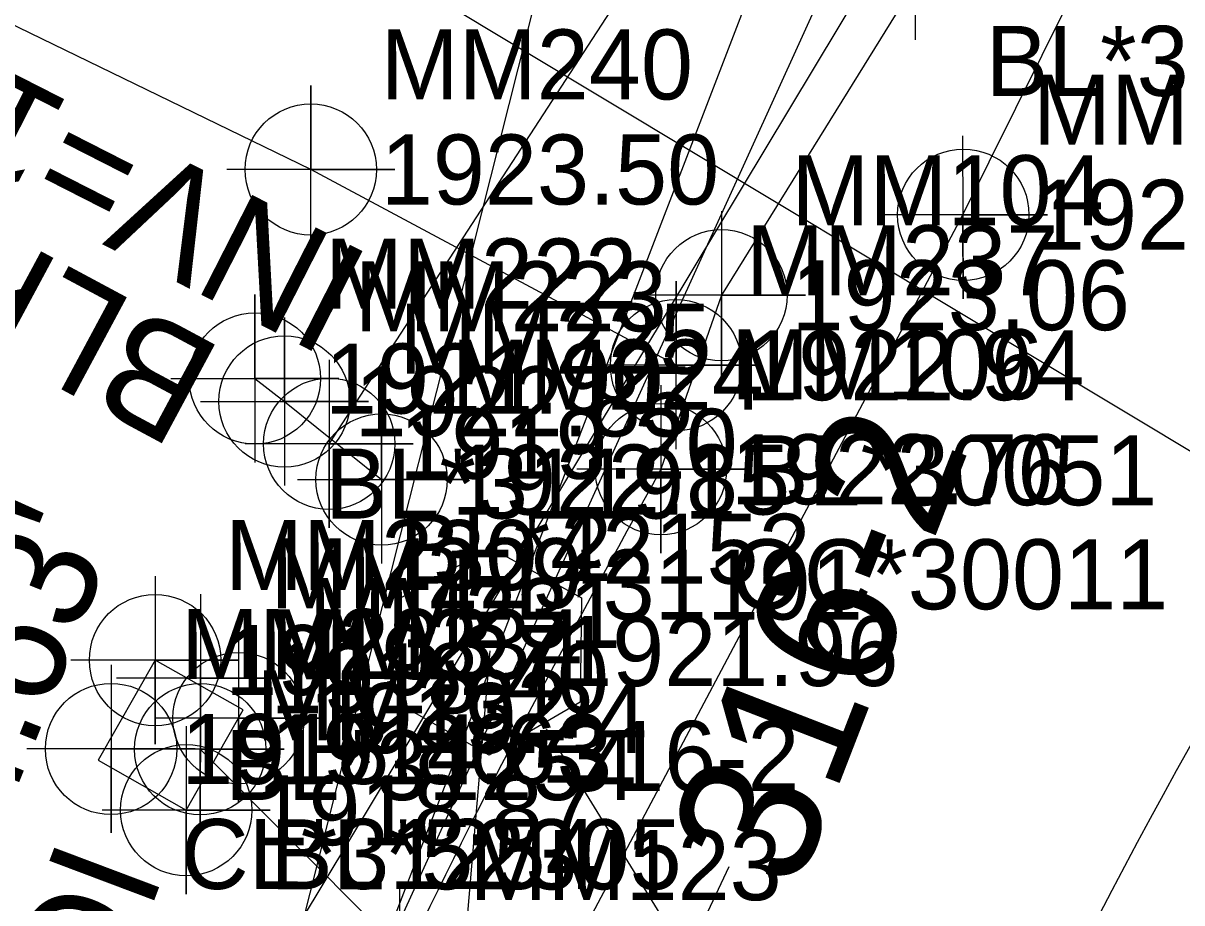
# Model space of a CAD drawing. Extents: x 1004514 to 1005247, y 553695 to 554706.
# Drawn here: x 1005003.62 to 1005044.98, y 554228.19 to 554259.6 of the extents above; entities that cross this region are included whole.
import ezdxf

# ---------------------------------------------------------------- set-up
doc = ezdxf.new("R2010")
doc.units = 0
for name, color, linetype in [('COGO Default Chain', 7, 'Continuous'), ('COGO Default Curve', 7, 'Continuous'), ('CTL Primary Horizontal and Vertical CELL', 7, 'Continuous'), ('CTL Primary Horizontal and Vertical Cogo Comment', 7, 'Continuous'), ('CTL Primary Horizontal and Vertical Cogo Elevation', 7, 'Continuous'), ('CTL Primary Horizontal and Vertical Cogo Number', 7, 'Continuous'), ('CTL Primary Horizontal and Vertical Leader', 7, 'Continuous'), ('CTL Primary Horizontal and Vertical Text', 7, 'Continuous'), ('Exist DTM Spot Elevation CELL', 7, 'Continuous'), ('Exist DTM Spot Elevation Cogo Elevation', 7, 'Continuous'), ('Exist DTM Spot Elevation Cogo Number', 7, 'Continuous'), ('Exist Horizontal Alignment', 7, 'Continuous'), ('Exist Right of Way Line', 7, 'Continuous'), ('Exist Roads Curbs', 7, 'Continuous'), ('Exist Roads EOP', 7, 'Continuous'), ('Exist Roads EOP Cogo Comment', 7, 'Continuous'), ('Exist Roads EOP Cogo Elevation', 7, 'Continuous'), ('Exist Roads EOP Cogo Number', 7, 'Continuous'), ('Exist Roads EOP Cogo Point CELL', 7, 'Continuous'), ('Exist Roads Soil', 7, 'Continuous'), ('Exist Roads Soil Cogo Comment', 7, 'Continuous'), ('Exist Roads Soil Cogo Elevation', 7, 'Continuous'), ('Exist Roads Soil Cogo Number', 7, 'Continuous'), ('Exist Roads Soil Cogo Point CELL', 7, 'Continuous'), ('Exist Structure Major Bridge WW', 7, 'Continuous'), ('Exist Structure Major Bridge WW Cogo Comment', 7, 'Continuous'), ('Exist Structure Major Bridge WW Cogo Elevation', 7, 'Continuous'), ('Exist Structure Major Bridge WW Cogo Number', 7, 'Continuous'), ('Exist Structure Major Bridge WW Cogo Point CELL', 7, 'Continuous'), ('Exist Structure Major Bridge WW Text', 7, 'Continuous'), ('Exist Structure Minor Drop Inlet', 7, 'Continuous'), ('Exist Structure Minor Drop Inlet Cogo Comment', 7, 'Continuous'), ('Exist Structure Minor Drop Inlet Cogo Elevation', 7, 'Continuous'), ('Exist Structure Minor Drop Inlet Cogo Number', 7, 'Continuous'), ('Exist Structure Minor Drop Inlet Cogo Point CELL', 7, 'Continuous'), ('Exist Structure Minor Drop Inlet Text', 7, 'Continuous'), ('Exist Structure Minor Pipes CMP 30 Inch', 7, 'Continuous'), ('Exist Structure Minor Pipes CMP 30 Inch Cogo Comment', 7, 'Continuous'), ('Exist Structure Minor Pipes CMP 30 Inch Cogo Elevation', 7, 'Continuous'), ('Exist Structure Minor Pipes CMP 30 Inch Cogo Number', 7, 'Continuous'), ('Exist Structure Minor Pipes CMP 30 Inch Cogo Point CELL', 7, 'Continuous'), ('Exist Structure Minor Pipes CMP 30 Inch Invert', 7, 'Continuous'), ('Exist Structure Minor Pipes RCP 15 Inch', 7, 'Continuous'), ('Exist Structure Minor Pipes RCP 15 Inch Cogo Comment', 7, 'Continuous'), ('Exist Structure Minor Pipes RCP 15 Inch Cogo Elevation', 7, 'Continuous'), ('Exist Structure Minor Pipes RCP 15 Inch Cogo Number', 7, 'Continuous'), ('Exist Structure Minor Pipes RCP 15 Inch Cogo Point CELL', 7, 'Continuous'), ('Exist Structure Minor Pipes RCP 15 Inch Invert', 7, 'Continuous'), ('Exist Utilities Telephone UG Conduit SUE LOS B', 7, 'Continuous'), ('Exist Utilities Telephone UG Conduit SUE LOS B Cogo Elevation', 7, 'Continuous'), ('Exist Utilities Telephone UG Conduit SUE LOS B Cogo Number', 7, 'Continuous'), ('Exist Utilities Telephone UG Conduit SUE LOS B Cogo Point CELL', 7, 'Continuous'), ('Exist Utilities Telephone UG FO SUE LOS C', 7, 'Continuous'), ('Old_Level_3', 7, 'Continuous'), ('Scratch_Level_3', 7, 'Continuous')]:
    doc.layers.add(name, color=color, linetype=linetype)

msp = doc.modelspace()

# ---------------------------------------------------------------- linework, layer by layer
at = {"layer": 'COGO Default Chain'}
msp.add_line((1004974.9, 553701.543), (1005020.282, 554237.182), dxfattribs=at)
msp.add_arc((1005209.198, 554141.741), 188, 143.26447, 181.15854, dxfattribs=at)
at = {"layer": 'COGO Default Curve'}
msp.add_arc((1005209.198, 554141.741), 188, 143.26447, 181.15854, dxfattribs=at)
at = {"layer": 'CTL Primary Horizontal and Vertical CELL'}
msp.add_line((1005020.282, 554237.182), (1005020.282, 554237.182), dxfattribs=at)
msp.add_lwpolyline([(1005017.051, 554239.054), (1005020.301, 554240.866), (1005023.551, 554239.079), (1005023.501, 554235.354), (1005020.251, 554233.466), (1005017.051, 554235.279)], close=True, dxfattribs=at)
at = {"layer": 'CTL Primary Horizontal and Vertical Leader'}
msp.add_lwpolyline([(1005022.291, 554234.394), (1005027.295, 554226.252), (1005028.822, 554229.491)], dxfattribs=at)
at = {"layer": 'Exist DTM Spot Elevation CELL'}
msp.add_lwpolyline([(1005009.944, 554239.21), (1005009.944, 554233.21), (1005009.944, 554236.21), (1005012.944, 554236.21), (1005006.944, 554236.21)], dxfattribs=at)
at = {"layer": 'Exist Horizontal Alignment'}
msp.add_arc((1005209.198, 554141.741), 188, 143.26447, 181.15854, dxfattribs=at)
at = {"layer": 'Exist Right of Way Line'}
msp.add_arc((1005209.198, 554141.741), 238, 143.26447, 181.15854, dxfattribs=at)
at = {"layer": 'Exist Roads Curbs'}
msp.add_spline([(1005075.03, 554240.325), (1005055.961, 554205.561), (1005046.997, 554176.639), (1005041.862, 554143.203), (1005041.439, 554133.575)], degree=3, dxfattribs=at)
at = {"layer": 'Exist Roads EOP'}
msp.add_lwpolyline([(1005042.326, 554267.369), (1005036.922, 554263.41), (1005028.544, 554249.886), (1005026.381, 554243.671)], dxfattribs=at)
for points in [[(1005026.381, 554243.671), (1005017.049, 554225.785), (1005004.478, 554185.698), (1005001.445, 554147.868), (1005001.025, 554103.612), (1005002.785, 554054.517)], [(1005074.494, 554240.581), (1005055.678, 554205.88), (1005046.35, 554176.623), (1005041.386, 554143.248), (1005040.93, 554132.857)]]:
    msp.add_spline(points, degree=3, dxfattribs=at)
at = {"layer": 'Exist Roads EOP Cogo Point CELL'}
for points in [[(1005028.544, 554252.886), (1005028.544, 554246.886), (1005028.544, 554249.886), (1005031.544, 554249.886), (1005025.544, 554249.886)], [(1005026.381, 554246.671), (1005026.381, 554240.671), (1005026.381, 554243.671), (1005029.381, 554243.671), (1005023.381, 554243.671)], [(1005017.049, 554228.785), (1005017.049, 554222.785), (1005017.049, 554225.785), (1005020.049, 554225.785), (1005014.049, 554225.785)]]:
    msp.add_lwpolyline(points, dxfattribs=at)
for centre in [(1005028.544, 554249.886), (1005026.381, 554243.671)]:
    msp.add_circle(centre, 2.344, dxfattribs=at)
at = {"layer": 'Exist Roads Soil'}
msp.add_lwpolyline([(1005026.922, 554247.386), (1005013.881, 554254.375), (1004980.46, 554270.626), (1004959.228, 554275.018)], dxfattribs=at)
at = {"layer": 'Exist Roads Soil Cogo Point CELL'}
for points in [[(1005035.476, 554259.003), (1005035.476, 554265.003), (1005035.476, 554262.003), (1005038.476, 554262.003), (1005032.476, 554262.003)], [(1005013.881, 554251.375), (1005013.881, 554257.375), (1005013.881, 554254.375), (1005016.881, 554254.375), (1005010.881, 554254.375)], [(1005026.922, 554244.386), (1005026.922, 554250.386), (1005026.922, 554247.386), (1005029.922, 554247.386), (1005023.922, 554247.386)]]:
    msp.add_lwpolyline(points, dxfattribs=at)
for centre in [(1005013.881, 554254.375), (1005026.922, 554247.386)]:
    msp.add_circle(centre, 2.344, dxfattribs=at)
at = {"layer": 'Exist Structure Major Bridge WW'}
msp.add_lwpolyline([(1005011.889, 554246.911), (1005012.944, 554246.095), (1005016.412, 554243.304)], dxfattribs=at)
at = {"layer": 'Exist Structure Major Bridge WW Cogo Point CELL'}
for points in [[(1005008.889, 554246.911), (1005014.889, 554246.911), (1005011.889, 554246.911), (1005011.889, 554249.911), (1005011.889, 554243.911)], [(1005009.944, 554246.095), (1005015.944, 554246.095), (1005012.944, 554246.095), (1005012.944, 554249.095), (1005012.944, 554243.095)], [(1005013.412, 554243.304), (1005019.412, 554243.304), (1005016.412, 554243.304), (1005016.412, 554246.304), (1005016.412, 554240.304)]]:
    msp.add_lwpolyline(points, dxfattribs=at)
for centre in [(1005011.889, 554246.911), (1005012.944, 554246.095), (1005016.412, 554243.304)]:
    msp.add_circle(centre, 2.344, dxfattribs=at)
at = {"layer": 'Exist Structure Minor Drop Inlet'}
msp.add_lwpolyline([(1005009.438, 554231.497), (1005011.467, 554235.075), (1005008.323, 554236.858), (1005006.294, 554233.28)], close=True, dxfattribs=at)
at = {"layer": 'Exist Structure Minor Drop Inlet Cogo Point CELL'}
for points in [[(1005008.323, 554239.858), (1005008.323, 554233.858), (1005008.323, 554236.858), (1005011.323, 554236.858), (1005005.323, 554236.858)], [(1005011.304, 554237.786), (1005011.304, 554231.786), (1005011.304, 554234.786), (1005014.304, 554234.786), (1005008.304, 554234.786)], [(1005006.752, 554236.683), (1005006.752, 554230.683), (1005006.752, 554233.683), (1005009.752, 554233.683), (1005003.752, 554233.683)], [(1005009.438, 554234.497), (1005009.438, 554228.497), (1005009.438, 554231.497), (1005012.438, 554231.497), (1005006.438, 554231.497)]]:
    msp.add_lwpolyline(points, dxfattribs=at)
for centre in [(1005008.323, 554236.858), (1005011.304, 554234.786), (1005006.752, 554233.683), (1005009.438, 554231.497)]:
    msp.add_circle(centre, 2.344, dxfattribs=at)
at = {"layer": 'Exist Structure Minor Pipes CMP 30 Inch'}
msp.add_line((1005009.937, 554233.672), (1005074.79, 554168.593), dxfattribs=at)
at = {"layer": 'Exist Structure Minor Pipes CMP 30 Inch Cogo Point CELL'}
msp.add_lwpolyline([(1005009.937, 554236.672), (1005009.937, 554230.672), (1005009.937, 554233.672), (1005012.937, 554233.672), (1005006.937, 554233.672)], dxfattribs=at)
msp.add_circle((1005009.937, 554233.672), 2.344, dxfattribs=at)
at = {"layer": 'Exist Structure Minor Pipes RCP 15 Inch'}
msp.add_line((1005014.54, 554244.581), (1005028.734, 554266.415), dxfattribs=at)
at = {"layer": 'Exist Structure Minor Pipes RCP 15 Inch Cogo Point CELL'}
msp.add_lwpolyline([(1005014.54, 554247.581), (1005014.54, 554241.581), (1005014.54, 554244.581), (1005017.54, 554244.581), (1005011.54, 554244.581)], dxfattribs=at)
msp.add_circle((1005014.54, 554244.581), 2.344, dxfattribs=at)
at = {"layer": 'Exist Utilities Telephone UG Conduit SUE LOS B'}
for points in [[(1004986.625, 553881.898), (1004994.172, 553936.442), (1004994.355, 553983.339), (1004992.834, 554032.196), (1004992.187, 554082.209), (1005000.242, 554139.11), (1005002.91, 554167.939), (1005012.741, 554216.936), (1005031.231, 554265.036), (1005060.708, 554304.647)], [(1004986.909, 553881.957), (1004994.669, 553936.387), (1004995.066, 553983.404), (1004993.502, 554032.182), (1004992.704, 554081.89), (1004999.846, 554139.17), (1005002.6, 554167.938), (1005012.391, 554217.264), (1005034.093, 554264.981), (1005060.823, 554304.66)], [(1004996.466, 553880.309), (1005003.636, 553934.419), (1005005.075, 553983.38), (1005003.635, 554031.726), (1005001.159, 554081.826), (1005001.307, 554137.229), (1005005.127, 554167.881), (1005016.898, 554214.508), (1005037.162, 554252.759), (1005044.72, 554267.983), (1005066.683, 554300.275)]]:
    msp.add_lwpolyline(points, dxfattribs=at)
at = {"layer": 'Exist Utilities Telephone UG Conduit SUE LOS B Cogo Point CELL'}
msp.add_lwpolyline([(1005037.146, 554255.574), (1005037.179, 554249.759), (1005037.162, 554252.759), (1005040.179, 554252.759), (1005034.179, 554252.759)], dxfattribs=at)
msp.add_circle((1005037.179, 554252.759), 2.344, dxfattribs=at)
at = {"layer": 'Exist Utilities Telephone UG FO SUE LOS C'}
msp.add_lwpolyline([(1004993.352, 553880.974), (1004999.906, 553935.306), (1005000.501, 553983.286), (1004999.325, 554031.271), (1004996.571, 554081.46), (1004996.427, 554140.051), (1004998.713, 554168.32), (1005009.154, 554220.252), (1005037.109, 554266.749), (1005065.185, 554302.194)], dxfattribs=at)
at = {"layer": 'Old_Level_3'}
msp.add_line((1004974.392, 554286.954), (1005076.106, 554225.778), dxfattribs=at)
at = {"layer": 'Scratch_Level_3'}
msp.add_line((1004952.617, 553985.711), (1005030.054, 554292.752), dxfattribs=at)

# ---------------------------------------------------------------- texts
at = {"layer": 'CTL Primary Horizontal and Vertical Cogo Comment'}
msp.add_text('316-2', height=2.5, dxfattribs=at).set_placement((1005022.782, 554232.182))
at = {"layer": 'CTL Primary Horizontal and Vertical Cogo Elevation'}
msp.add_text('1921.96', height=2.5, dxfattribs=at).set_placement((1005022.782, 554235.932))
at = {"layer": 'CTL Primary Horizontal and Vertical Cogo Number'}
msp.add_text('2', height=2.5, dxfattribs=at).set_placement((1005022.782, 554239.682))
at = {"layer": 'CTL Primary Horizontal and Vertical Text'}
msp.add_text('316-2', height=5, rotation=68.8153, dxfattribs=at).set_placement((1005031.236, 554228.526))
at = {"layer": 'Exist DTM Spot Elevation Cogo Elevation'}
msp.add_text('1918.40', height=2.5, dxfattribs=at).set_placement((1005012.444, 554234.96))
at = {"layer": 'Exist DTM Spot Elevation Cogo Number'}
msp.add_text('MM229', height=2.5, dxfattribs=at).set_placement((1005012.444, 554238.71))
at = {"layer": 'Exist Roads EOP Cogo Comment'}
msp.add_text('OC*30011', height=2.5, dxfattribs=at).set_placement((1005028.881, 554238.671))
at = {"layer": 'Exist Roads EOP Cogo Elevation'}
for s, p in [('1923.06', (1005031.044, 554248.636)), ('1922.76', (1005028.881, 554242.421))]:
    msp.add_text(s, height=2.5, dxfattribs=at).set_placement(p)
at = {"layer": 'Exist Roads EOP Cogo Number'}
for s, p in [('MM104', (1005031.044, 554252.386)), ('MM106', (1005028.881, 554246.171)), ('MM123', (1005019.549, 554228.285))]:
    msp.add_text(s, height=2.5, dxfattribs=at).set_placement(p)
at = {"layer": 'Exist Roads Soil Cogo Comment'}
for s, p in [('BL*30052', (1005037.976, 554257.003)), ('BL*30051', (1005029.422, 554242.386))]:
    msp.add_text(s, height=2.5, dxfattribs=at).set_placement(p)
at = {"layer": 'Exist Roads Soil Cogo Elevation'}
for s, p in [('1923.50', (1005016.381, 554253.125)), ('1922.94', (1005029.422, 554246.136))]:
    msp.add_text(s, height=2.5, dxfattribs=at).set_placement(p)
at = {"layer": 'Exist Roads Soil Cogo Number'}
for s, p in [('MM240', (1005016.381, 554256.875)), ('MM237', (1005029.422, 554249.886))]:
    msp.add_text(s, height=2.5, dxfattribs=at).set_placement(p)
at = {"layer": 'Exist Structure Major Bridge WW Cogo Comment'}
for s, p in [('BL*31191', (1005014.389, 554241.911)), ('EL*31191', (1005018.912, 554238.304))]:
    msp.add_text(s, height=2.5, dxfattribs=at).set_placement(p)
at = {"layer": 'Exist Structure Major Bridge WW Cogo Elevation'}
for s, p in [('1921.90', (1005014.389, 554245.661)), ('1922.85', (1005015.444, 554244.845)), ('1922.85', (1005018.912, 554242.054))]:
    msp.add_text(s, height=2.5, dxfattribs=at).set_placement(p)
at = {"layer": 'Exist Structure Major Bridge WW Cogo Number'}
for s, p in [('MM222', (1005014.389, 554249.411)), ('MM223', (1005015.444, 554248.595)), ('MM224', (1005018.912, 554245.804))]:
    msp.add_text(s, height=2.5, dxfattribs=at).set_placement(p)
at = {"layer": 'Exist Structure Major Bridge WW Text'}
msp.add_text('BLK HW', height=4, rotation=151.7681, dxfattribs=at).set_placement((1005010.844, 554247.917))
at = {"layer": 'Exist Structure Minor Drop Inlet Cogo Comment'}
for s, p in [('BL*31254', (1005010.823, 554231.858)), ('CL*31254', (1005009.252, 554228.683))]:
    msp.add_text(s, height=2.5, dxfattribs=at).set_placement(p)
at = {"layer": 'Exist Structure Minor Drop Inlet Cogo Elevation'}
for s, p in [('1919.27', (1005010.823, 554235.608)), ('1919.24', (1005013.804, 554233.536)), ('1918.86', (1005009.252, 554232.433)), ('1918.87', (1005011.938, 554230.247))]:
    msp.add_text(s, height=2.5, dxfattribs=at).set_placement(p)
at = {"layer": 'Exist Structure Minor Drop Inlet Cogo Number'}
for s, p in [('MM230', (1005010.823, 554239.358)), ('MM231', (1005013.804, 554237.286)), ('MM233', (1005009.252, 554236.183)), ('MM232', (1005011.938, 554233.997))]:
    msp.add_text(s, height=2.5, dxfattribs=at).set_placement(p)
at = {"layer": 'Exist Structure Minor Drop Inlet Text'}
msp.add_text('CONC DI', height=4, rotation=69.358, dxfattribs=at).set_placement((1005000.682, 554208.075))
at = {"layer": 'Exist Structure Minor Pipes CMP 30 Inch Cogo Comment'}
msp.add_text('BL*52305', height=2.5, dxfattribs=at).set_placement((1005012.437, 554228.672))
at = {"layer": 'Exist Structure Minor Pipes CMP 30 Inch Cogo Elevation'}
msp.add_text('1914.63', height=2.5, dxfattribs=at).set_placement((1005012.437, 554232.422))
at = {"layer": 'Exist Structure Minor Pipes CMP 30 Inch Cogo Number'}
msp.add_text('MM234', height=2.5, dxfattribs=at).set_placement((1005012.437, 554236.172))
at = {"layer": 'Exist Structure Minor Pipes CMP 30 Inch Invert'}
msp.add_text("INV=1914.63'", height=4, rotation=68.3068, dxfattribs=at).set_placement((1004995.039, 554211.294))
at = {"layer": 'Exist Structure Minor Pipes RCP 15 Inch Cogo Comment'}
msp.add_text('BL*42152', height=2.5, dxfattribs=at).set_placement((1005017.04, 554239.581))
at = {"layer": 'Exist Structure Minor Pipes RCP 15 Inch Cogo Elevation'}
msp.add_text('1919.20', height=2.5, dxfattribs=at).set_placement((1005017.04, 554243.331))
at = {"layer": 'Exist Structure Minor Pipes RCP 15 Inch Cogo Number'}
msp.add_text('MM225', height=2.5, dxfattribs=at).set_placement((1005017.04, 554247.081))
at = {"layer": 'Exist Structure Minor Pipes RCP 15 Inch Invert'}
msp.add_text("INV=1919.20'", height=4, rotation=153.0004, dxfattribs=at).set_placement((1005016.168, 554251.237))
at = {"layer": 'Exist Utilities Telephone UG Conduit SUE LOS B Cogo Elevation'}
msp.add_text('1923.37', height=2.5, dxfattribs=at).set_placement((1005039.662, 554251.509))
at = {"layer": 'Exist Utilities Telephone UG Conduit SUE LOS B Cogo Number'}
msp.add_text('MM394', height=2.5, dxfattribs=at).set_placement((1005039.662, 554255.259))

doc.saveas('drawing.dxf')
